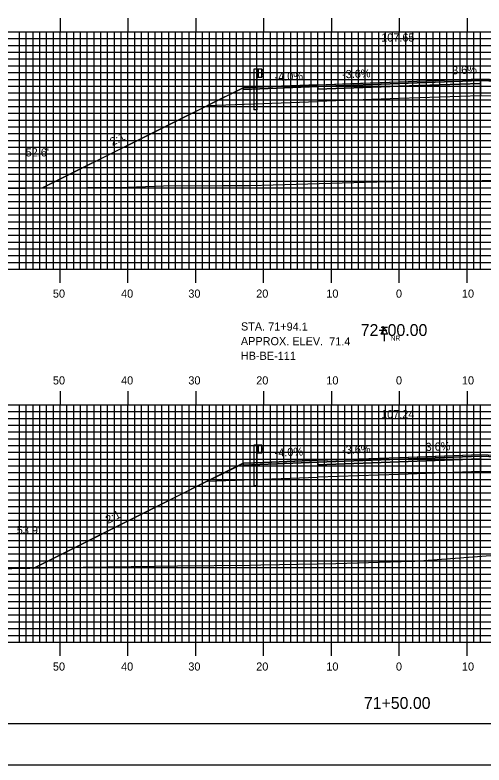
# Model space of a CAD drawing. Extents: x 1760610 to 1760954, y 442591 to 442811.
# Drawn here: x 1760719.5 to 1760788.7, y 442590.5 to 442701.2 of the extents above; entities that cross this region are included whole.
import ezdxf

# ---------------------------------------------------------------- set-up
doc = ezdxf.new("R2010")
doc.units = 0
for name, color, linetype in [('ANNOTATION', 7, 'Continuous'), ('BORDER', 7, 'Continuous'), ('BORING - NO REFUSAL', 7, 'Continuous'), ('D_Guardrail_Beam_Lt', 7, 'Continuous'), ('D_Roadway_Centerline', 7, 'Continuous'), ('D_Roadway_Centerline_Text', 7, 'Continuous'), ('D_Roadway_Edge_Shoulder', 7, 'Continuous'), ('D_Roadway_Edge_TW', 7, 'Continuous'), ('D_Roadway_Pavement', 7, 'Continuous'), ('D_Roadway_SlopeLines', 7, 'Continuous'), ('D_Roadway_SubGrade', 7, 'Continuous'), ('D_Text_Standard', 7, 'Continuous'), ('H_V ANNOTATION', 7, 'Continuous'), ('MAJOR', 7, 'Continuous'), ('MINOR', 7, 'Continuous'), ('PLOT BOUNDARY', 7, 'Continuous'), ('S_Roadway_Centerline', 7, 'Continuous')]:
    doc.layers.add(name, color=color, linetype=linetype)

msp = doc.modelspace()

# ---------------------------------------------------------------- linework, layer by layer
at = {"layer": 'BORDER'}
msp.add_lwpolyline([(1760626.61, 442596.67), (1760946.61, 442596.67), (1760946.61, 442806.67), (1760626.61, 442806.67)], close=True, dxfattribs=at)
at = {"layer": 'BORING - NO REFUSAL'}
for p, q in [((1760774.49, 442655.07), (1760773.53, 442655.07)), ((1760774.01, 442654.11), (1760774.01, 442653.05))]:
    msp.add_line(p, q, dxfattribs=at)
msp.add_lwpolyline([(1760774.01, 442655.07), (1760774.49, 442654.11), (1760773.53, 442654.11)], close=True, dxfattribs=at)
at = {"layer": 'D_Guardrail_Beam_Lt'}
for p, q in [((1760754.78, 442693.15), (1760754.78, 442687.15)), ((1760755.26, 442693.15), (1760754.78, 442693.15)), ((1760755.94, 442693.15), (1760755.26, 442693.15)), ((1760755.26, 442693.15), (1760755.26, 442691.98)), ((1760755.32, 442693.15), (1760755.32, 442691.98)), ((1760755.42, 442693.15), (1760755.42, 442691.98)), ((1760755.94, 442691.98), (1760755.94, 442693.15)), ((1760755.94, 442693.06), (1760756.02, 442693.05)), ((1760756.18, 442692.8), (1760755.98, 442692.66)), ((1760756.03, 442693.04), (1760756.18, 442692.94)), ((1760755.26, 442691.98), (1760755.94, 442691.98)), ((1760755.28, 442687.15), (1760755.28, 442691.98)), ((1760756.02, 442692.08), (1760755.94, 442692.06)), ((1760755.95, 442692.6), (1760755.95, 442692.53)), ((1760755.98, 442692.46), (1760756.18, 442692.33)), ((1760756.18, 442692.18), (1760756.03, 442692.08)), ((1760755.28, 442687.15), (1760754.78, 442687.15)), ((1760754.78, 442637.74), (1760754.78, 442631.74)), ((1760755.26, 442637.74), (1760754.78, 442637.74)), ((1760755.94, 442637.74), (1760755.26, 442637.74)), ((1760755.26, 442637.74), (1760755.26, 442636.57)), ((1760755.32, 442637.74), (1760755.32, 442636.57)), ((1760755.42, 442637.74), (1760755.42, 442636.57)), ((1760755.94, 442636.57), (1760755.94, 442637.74)), ((1760755.94, 442637.66), (1760756.02, 442637.64)), ((1760756.18, 442637.39), (1760755.98, 442637.26)), ((1760756.03, 442637.64), (1760756.18, 442637.54)), ((1760755.26, 442636.57), (1760755.94, 442636.57)), ((1760755.28, 442631.74), (1760755.28, 442636.57)), ((1760756.02, 442636.67), (1760755.94, 442636.66)), ((1760755.95, 442637.19), (1760755.95, 442637.12)), ((1760755.98, 442637.06), (1760756.18, 442636.92)), ((1760756.18, 442636.78), (1760756.03, 442636.68)), ((1760755.28, 442631.74), (1760754.78, 442631.74))]:
    msp.add_line(p, q, dxfattribs=at)
for centre, major_axis, start_param, end_param in [((1760756.03, 442692.6), (-0.0789, 0), 5.323254, 6.283185), ((1760756.01, 442693.01), (0.0417, 0), 0.959931, 1.376053), ((1760756.13, 442692.87), (0.0877, 0), 5.323254, 7.243116), ((1760756.03, 442692.53), (-0.0789, 0), 6.283185, 7.243116), ((1760756.01, 442692.12), (0.0417, 0), 4.907132, 5.323254), ((1760756.13, 442692.26), (0.0877, 0), 5.323254, 7.243116), ((1760756.01, 442637.6), (0.0417, 0), 0.959931, 1.376053), ((1760756.13, 442637.46), (0.0877, 0), 5.323254, 7.243116), ((1760756.03, 442637.19), (-0.0789, 0), 5.323254, 6.283185), ((1760756.03, 442637.12), (-0.0789, 0), 6.283185, 7.243116), ((1760756.01, 442636.71), (0.0417, 0), 4.907132, 5.323254), ((1760756.13, 442636.85), (0.0877, 0), 5.323254, 7.243116)]:
    msp.add_ellipse(centre, major_axis=major_axis, ratio=0.995501, start_param=start_param, end_param=end_param, dxfattribs=at)
at = {"layer": 'D_Roadway_Centerline'}
for points in [[(1760723.62, 442675.65), (1760747.92, 442687.8), (1760747.92, 442687.8), (1760749.52, 442688.6), (1760753.21, 442690.44), (1760753.22, 442690.44), (1760756.21, 442690.56), (1760756.22, 442690.56), (1760764.21, 442690.88), (1760764.23, 442690.88), (1760769.08, 442691.06), (1760776.21, 442691.32), (1760776.21, 442691.32), (1760784.04, 442691.6), (1760788.21, 442691.75), (1760788.22, 442691.75), (1760790.81, 442691.64), (1760796.21, 442691.43), (1760796.21, 442691.43), (1760797.9, 442691.36), (1760799.21, 442691.31), (1760803.96, 442688.93), (1760828.33, 442676.75), (1760828.33, 442676.75)], [(1760722.32, 442619.59), (1760722.34, 442619.6), (1760727.43, 442622.15), (1760747.91, 442632.39), (1760747.92, 442632.39), (1760751.51, 442634.19), (1760753.21, 442635.03), (1760753.21, 442635.04), (1760756.2, 442635.16), (1760756.21, 442635.16), (1760756.25, 442635.16), (1760764.21, 442635.48), (1760764.22, 442635.48), (1760776.21, 442635.91), (1760776.22, 442635.91), (1760780.32, 442636.06), (1760788.21, 442636.34), (1760789.01, 442636.31)]]:
    msp.add_lwpolyline(points, dxfattribs=at)
at = {"layer": 'D_Roadway_Edge_Shoulder'}
for points in [[(1760788.21, 442691.75), (1760796.21, 442691.43), (1760796.21, 442691.43), (1760799.21, 442691.31), (1760799.21, 442691.06), (1760788.21, 442691.5)], [(1760764.21, 442690.88), (1760756.21, 442690.56), (1760756.21, 442690.56), (1760753.21, 442690.44), (1760753.21, 442690.19), (1760764.21, 442690.63)], [(1760788.21, 442636.34), (1760796.21, 442636.02), (1760796.21, 442636.02), (1760799.21, 442635.9), (1760799.21, 442635.65), (1760788.21, 442636.09)], [(1760764.21, 442635.48), (1760756.21, 442635.16), (1760756.21, 442635.16), (1760753.21, 442635.04), (1760753.21, 442634.79), (1760764.21, 442635.23)]]:
    msp.add_lwpolyline(points, close=True, dxfattribs=at)
at = {"layer": 'D_Roadway_Edge_TW'}
for points in [[(1760764.21, 442690.63), (1760764.21, 442690.88), (1760776.21, 442691.32), (1760788.21, 442691.75), (1760788.21, 442691.5), (1760776.21, 442691.07)], [(1760788.21, 442691.75), (1760788.21, 442691.75), (1760788.21, 442691.5), (1760788.21, 442691.5)], [(1760764.21, 442635.23), (1760764.21, 442635.48), (1760776.21, 442635.91), (1760788.21, 442636.34), (1760788.21, 442636.09), (1760776.21, 442635.66)], [(1760788.21, 442636.34), (1760788.21, 442636.34), (1760788.21, 442636.09), (1760788.21, 442636.09)]]:
    msp.add_lwpolyline(points, close=True, dxfattribs=at)
at = {"layer": 'D_Roadway_Pavement'}
for points in [[(1760764.21, 442690.22), (1760764.21, 442690.63), (1760776.21, 442691.07), (1760788.21, 442691.5), (1760788.21, 442691.08), (1760776.21, 442690.65)], [(1760788.21, 442691.5), (1760788.21, 442691.5), (1760788.21, 442691.08), (1760788.21, 442691.08)], [(1760764.21, 442634.81), (1760764.21, 442635.23), (1760776.21, 442635.66), (1760788.21, 442636.09), (1760788.21, 442635.68), (1760776.21, 442635.24)], [(1760788.21, 442636.09), (1760788.21, 442636.09), (1760788.21, 442635.68), (1760788.21, 442635.68)]]:
    msp.add_lwpolyline(points, close=True, dxfattribs=at)
for points in [[(1760764.21, 442690.63), (1760764.21, 442690.22)], [(1760788.21, 442691.5), (1760788.21, 442691.08)], [(1760788.21, 442691.5), (1760788.21, 442691.08)], [(1760764.21, 442635.23), (1760764.21, 442634.81)], [(1760788.21, 442636.09), (1760788.21, 442635.68)], [(1760788.21, 442636.09), (1760788.21, 442635.68)]]:
    msp.add_lwpolyline(points, dxfattribs=at)
at = {"layer": 'D_Roadway_SlopeLines'}
for points in [[(1760753.21, 442690.44), (1760723.62, 442675.65)], [(1760753.21, 442635.04), (1760722.32, 442619.59)]]:
    msp.add_lwpolyline(points, dxfattribs=at)
at = {"layer": 'D_Roadway_SubGrade'}
for points in [[(1760764.21, 442690.22), (1760764.21, 442690.63), (1760753.21, 442690.19), (1760753.21, 442690.44), (1760747.92, 442687.8), (1760764.21, 442688.38)], [(1760764.21, 442688.38), (1760764.21, 442690.22), (1760776.21, 442690.65), (1760788.21, 442691.08), (1760788.21, 442689.25), (1760776.21, 442688.82)], [(1760788.21, 442691.08), (1760788.21, 442691.5), (1760799.21, 442691.06), (1760799.21, 442691.31), (1760803.96, 442688.93), (1760788.21, 442689.25)], [(1760788.21, 442691.08), (1760788.21, 442691.08), (1760788.21, 442689.25), (1760788.21, 442689.25)], [(1760764.21, 442634.81), (1760764.21, 442635.23), (1760753.21, 442634.79), (1760753.21, 442635.04), (1760747.92, 442632.39), (1760764.21, 442632.98)], [(1760764.21, 442632.98), (1760764.21, 442634.81), (1760776.21, 442635.24), (1760788.21, 442635.68), (1760788.21, 442633.84), (1760776.21, 442633.41)], [(1760788.21, 442635.68), (1760788.21, 442636.09), (1760799.21, 442635.65), (1760799.21, 442635.9), (1760803.96, 442633.53), (1760788.21, 442633.84)], [(1760788.21, 442635.68), (1760788.21, 442635.68), (1760788.21, 442633.84), (1760788.21, 442633.84)]]:
    msp.add_lwpolyline(points, close=True, dxfattribs=at)
at = {"layer": 'MAJOR'}
for p, q in [((1760726.21, 442700.67), (1760726.21, 442698.67)), ((1760736.21, 442700.67), (1760736.21, 442698.67)), ((1760746.21, 442700.67), (1760746.21, 442698.67)), ((1760756.21, 442700.67), (1760756.21, 442698.67)), ((1760766.21, 442700.67), (1760766.21, 442698.67)), ((1760776.21, 442700.67), (1760776.21, 442698.67)), ((1760786.21, 442700.67), (1760786.21, 442698.67)), ((1760636.21, 442698.67), (1760916.21, 442698.67)), ((1760636.21, 442698.67), (1760916.21, 442698.67)), ((1760726.21, 442663.67), (1760726.21, 442698.67)), ((1760736.21, 442663.67), (1760736.21, 442698.67)), ((1760746.21, 442663.67), (1760746.21, 442698.67)), ((1760756.21, 442663.67), (1760756.21, 442698.67)), ((1760766.21, 442663.67), (1760766.21, 442698.67)), ((1760776.21, 442663.67), (1760776.21, 442698.67)), ((1760786.21, 442663.67), (1760786.21, 442698.67)), ((1760636.21, 442693.67), (1760916.21, 442693.67)), ((1760636.21, 442688.67), (1760916.21, 442688.67)), ((1760636.21, 442683.67), (1760916.21, 442683.67)), ((1760636.21, 442678.67), (1760916.21, 442678.67)), ((1760636.21, 442673.67), (1760916.21, 442673.67)), ((1760636.21, 442668.67), (1760916.21, 442668.67)), ((1760636.21, 442663.67), (1760916.21, 442663.67)), ((1760636.21, 442663.67), (1760916.21, 442663.67)), ((1760726.21, 442661.66), (1760726.21, 442663.67)), ((1760736.21, 442661.66), (1760736.21, 442663.67)), ((1760746.21, 442661.66), (1760746.21, 442663.67)), ((1760756.21, 442661.66), (1760756.21, 442663.67)), ((1760766.21, 442661.66), (1760766.21, 442663.67)), ((1760776.21, 442661.66), (1760776.21, 442663.67)), ((1760786.21, 442661.66), (1760786.21, 442663.67)), ((1760726.21, 442645.67), (1760726.21, 442643.67)), ((1760736.21, 442645.67), (1760736.21, 442643.67)), ((1760746.21, 442645.67), (1760746.21, 442643.67)), ((1760756.21, 442645.67), (1760756.21, 442643.67)), ((1760766.21, 442645.67), (1760766.21, 442643.67)), ((1760776.21, 442645.67), (1760776.21, 442643.67)), ((1760786.21, 442645.67), (1760786.21, 442643.67)), ((1760636.21, 442643.67), (1760916.21, 442643.67)), ((1760636.21, 442643.67), (1760916.21, 442643.67)), ((1760726.21, 442608.67), (1760726.21, 442643.67)), ((1760736.21, 442608.67), (1760736.21, 442643.67)), ((1760746.21, 442608.67), (1760746.21, 442643.67)), ((1760756.21, 442608.67), (1760756.21, 442643.67)), ((1760766.21, 442608.67), (1760766.21, 442643.67)), ((1760776.21, 442608.67), (1760776.21, 442643.67)), ((1760786.21, 442608.67), (1760786.21, 442643.67)), ((1760636.21, 442638.67), (1760916.21, 442638.67)), ((1760636.21, 442633.67), (1760916.21, 442633.67)), ((1760636.21, 442628.67), (1760916.21, 442628.67)), ((1760636.21, 442623.67), (1760916.21, 442623.67)), ((1760636.21, 442618.67), (1760916.21, 442618.67)), ((1760636.21, 442613.67), (1760916.21, 442613.67)), ((1760636.21, 442608.67), (1760916.21, 442608.67)), ((1760636.21, 442608.67), (1760916.21, 442608.67)), ((1760726.21, 442606.66), (1760726.21, 442608.67)), ((1760736.21, 442606.66), (1760736.21, 442608.67)), ((1760746.21, 442606.66), (1760746.21, 442608.67)), ((1760756.21, 442606.66), (1760756.21, 442608.67)), ((1760766.21, 442606.66), (1760766.21, 442608.67)), ((1760776.21, 442606.66), (1760776.21, 442608.67)), ((1760786.21, 442606.66), (1760786.21, 442608.67))]:
    msp.add_line(p, q, dxfattribs=at)
at = {"layer": 'MINOR'}
for p, q in [((1760720.21, 442663.67), (1760720.21, 442698.67)), ((1760721.21, 442663.67), (1760721.21, 442698.67)), ((1760722.21, 442663.67), (1760722.21, 442698.67)), ((1760723.21, 442663.67), (1760723.21, 442698.67)), ((1760724.21, 442663.67), (1760724.21, 442698.67)), ((1760725.21, 442663.67), (1760725.21, 442698.67)), ((1760727.21, 442663.67), (1760727.21, 442698.67)), ((1760728.21, 442663.67), (1760728.21, 442698.67)), ((1760729.21, 442663.67), (1760729.21, 442698.67)), ((1760730.21, 442663.67), (1760730.21, 442698.67)), ((1760731.21, 442663.67), (1760731.21, 442698.67)), ((1760732.21, 442663.67), (1760732.21, 442698.67)), ((1760733.21, 442663.67), (1760733.21, 442698.67)), ((1760734.21, 442663.67), (1760734.21, 442698.67)), ((1760735.21, 442663.67), (1760735.21, 442698.67)), ((1760737.21, 442663.67), (1760737.21, 442698.67)), ((1760738.21, 442663.67), (1760738.21, 442698.67)), ((1760739.21, 442663.67), (1760739.21, 442698.67)), ((1760740.21, 442663.67), (1760740.21, 442698.67)), ((1760741.21, 442663.67), (1760741.21, 442698.67)), ((1760742.21, 442663.67), (1760742.21, 442698.67)), ((1760743.21, 442663.67), (1760743.21, 442698.67)), ((1760744.21, 442663.67), (1760744.21, 442698.67)), ((1760745.21, 442663.67), (1760745.21, 442698.67)), ((1760747.21, 442663.67), (1760747.21, 442698.67)), ((1760748.21, 442663.67), (1760748.21, 442698.67)), ((1760749.21, 442663.67), (1760749.21, 442698.67)), ((1760750.21, 442663.67), (1760750.21, 442698.67)), ((1760751.21, 442663.67), (1760751.21, 442698.67)), ((1760752.21, 442663.67), (1760752.21, 442698.67)), ((1760753.21, 442663.67), (1760753.21, 442698.67)), ((1760754.21, 442663.67), (1760754.21, 442698.67)), ((1760755.21, 442663.67), (1760755.21, 442698.67)), ((1760757.21, 442663.67), (1760757.21, 442698.67)), ((1760758.21, 442663.67), (1760758.21, 442698.67)), ((1760759.21, 442663.67), (1760759.21, 442698.67)), ((1760760.21, 442663.67), (1760760.21, 442698.67)), ((1760761.21, 442663.67), (1760761.21, 442698.67)), ((1760762.21, 442663.67), (1760762.21, 442698.67)), ((1760763.21, 442663.67), (1760763.21, 442698.67)), ((1760764.21, 442663.67), (1760764.21, 442698.67)), ((1760765.21, 442663.67), (1760765.21, 442698.67)), ((1760767.21, 442663.67), (1760767.21, 442698.67)), ((1760768.21, 442663.67), (1760768.21, 442698.67)), ((1760769.21, 442663.67), (1760769.21, 442698.67)), ((1760770.21, 442663.67), (1760770.21, 442698.67)), ((1760771.21, 442663.67), (1760771.21, 442698.67)), ((1760772.21, 442663.67), (1760772.21, 442698.67)), ((1760773.21, 442663.67), (1760773.21, 442698.67)), ((1760774.21, 442663.67), (1760774.21, 442698.67)), ((1760775.21, 442663.67), (1760775.21, 442698.67)), ((1760777.21, 442663.67), (1760777.21, 442698.67)), ((1760778.21, 442663.67), (1760778.21, 442698.67)), ((1760779.21, 442663.67), (1760779.21, 442698.67)), ((1760780.21, 442663.67), (1760780.21, 442698.67)), ((1760781.21, 442663.67), (1760781.21, 442698.67)), ((1760782.21, 442663.67), (1760782.21, 442698.67)), ((1760783.21, 442663.67), (1760783.21, 442698.67)), ((1760784.21, 442663.67), (1760784.21, 442698.67)), ((1760785.21, 442663.67), (1760785.21, 442698.67)), ((1760787.21, 442663.67), (1760787.21, 442698.67)), ((1760788.21, 442663.67), (1760788.21, 442698.67)), ((1760636.21, 442697.67), (1760916.21, 442697.67)), ((1760636.21, 442696.67), (1760916.21, 442696.67)), ((1760636.21, 442695.67), (1760916.21, 442695.67)), ((1760636.21, 442694.67), (1760916.21, 442694.67)), ((1760636.21, 442692.67), (1760916.21, 442692.67)), ((1760636.21, 442691.67), (1760916.21, 442691.67)), ((1760636.21, 442690.67), (1760916.21, 442690.67)), ((1760636.21, 442689.67), (1760916.21, 442689.67)), ((1760636.21, 442687.67), (1760916.21, 442687.67)), ((1760636.21, 442686.67), (1760916.21, 442686.67)), ((1760636.21, 442685.67), (1760916.21, 442685.67)), ((1760636.21, 442684.67), (1760916.21, 442684.67)), ((1760636.21, 442682.67), (1760916.21, 442682.67)), ((1760636.21, 442681.67), (1760916.21, 442681.67)), ((1760636.21, 442680.67), (1760916.21, 442680.67)), ((1760636.21, 442679.67), (1760916.21, 442679.67)), ((1760636.21, 442677.67), (1760916.21, 442677.67)), ((1760636.21, 442676.67), (1760916.21, 442676.67)), ((1760636.21, 442675.67), (1760916.21, 442675.67)), ((1760636.21, 442674.67), (1760916.21, 442674.67)), ((1760636.21, 442672.67), (1760916.21, 442672.67)), ((1760636.21, 442671.67), (1760916.21, 442671.67)), ((1760636.21, 442670.67), (1760916.21, 442670.67)), ((1760636.21, 442669.67), (1760916.21, 442669.67)), ((1760636.21, 442667.67), (1760916.21, 442667.67)), ((1760636.21, 442666.67), (1760916.21, 442666.67)), ((1760636.21, 442665.67), (1760916.21, 442665.67)), ((1760636.21, 442664.67), (1760916.21, 442664.67)), ((1760720.21, 442608.67), (1760720.21, 442643.67)), ((1760721.21, 442608.67), (1760721.21, 442643.67)), ((1760722.21, 442608.67), (1760722.21, 442643.67)), ((1760723.21, 442608.67), (1760723.21, 442643.67)), ((1760724.21, 442608.67), (1760724.21, 442643.67)), ((1760725.21, 442608.67), (1760725.21, 442643.67)), ((1760727.21, 442608.67), (1760727.21, 442643.67)), ((1760728.21, 442608.67), (1760728.21, 442643.67)), ((1760729.21, 442608.67), (1760729.21, 442643.67)), ((1760730.21, 442608.67), (1760730.21, 442643.67)), ((1760731.21, 442608.67), (1760731.21, 442643.67)), ((1760732.21, 442608.67), (1760732.21, 442643.67)), ((1760733.21, 442608.67), (1760733.21, 442643.67)), ((1760734.21, 442608.67), (1760734.21, 442643.67)), ((1760735.21, 442608.67), (1760735.21, 442643.67)), ((1760737.21, 442608.67), (1760737.21, 442643.67)), ((1760738.21, 442608.67), (1760738.21, 442643.67)), ((1760739.21, 442608.67), (1760739.21, 442643.67)), ((1760740.21, 442608.67), (1760740.21, 442643.67)), ((1760741.21, 442608.67), (1760741.21, 442643.67)), ((1760742.21, 442608.67), (1760742.21, 442643.67)), ((1760743.21, 442608.67), (1760743.21, 442643.67)), ((1760744.21, 442608.67), (1760744.21, 442643.67)), ((1760745.21, 442608.67), (1760745.21, 442643.67)), ((1760747.21, 442608.67), (1760747.21, 442643.67)), ((1760748.21, 442608.67), (1760748.21, 442643.67)), ((1760749.21, 442608.67), (1760749.21, 442643.67)), ((1760750.21, 442608.67), (1760750.21, 442643.67)), ((1760751.21, 442608.67), (1760751.21, 442643.67)), ((1760752.21, 442608.67), (1760752.21, 442643.67)), ((1760753.21, 442608.67), (1760753.21, 442643.67)), ((1760754.21, 442608.67), (1760754.21, 442643.67)), ((1760755.21, 442608.67), (1760755.21, 442643.67)), ((1760757.21, 442608.67), (1760757.21, 442643.67)), ((1760758.21, 442608.67), (1760758.21, 442643.67)), ((1760759.21, 442608.67), (1760759.21, 442643.67)), ((1760760.21, 442608.67), (1760760.21, 442643.67)), ((1760761.21, 442608.67), (1760761.21, 442643.67)), ((1760762.21, 442608.67), (1760762.21, 442643.67)), ((1760763.21, 442608.67), (1760763.21, 442643.67)), ((1760764.21, 442608.67), (1760764.21, 442643.67)), ((1760765.21, 442608.67), (1760765.21, 442643.67)), ((1760767.21, 442608.67), (1760767.21, 442643.67)), ((1760768.21, 442608.67), (1760768.21, 442643.67)), ((1760769.21, 442608.67), (1760769.21, 442643.67)), ((1760770.21, 442608.67), (1760770.21, 442643.67)), ((1760771.21, 442608.67), (1760771.21, 442643.67)), ((1760772.21, 442608.67), (1760772.21, 442643.67)), ((1760773.21, 442608.67), (1760773.21, 442643.67)), ((1760774.21, 442608.67), (1760774.21, 442643.67)), ((1760775.21, 442608.67), (1760775.21, 442643.67)), ((1760777.21, 442608.67), (1760777.21, 442643.67)), ((1760778.21, 442608.67), (1760778.21, 442643.67)), ((1760779.21, 442608.67), (1760779.21, 442643.67)), ((1760780.21, 442608.67), (1760780.21, 442643.67)), ((1760781.21, 442608.67), (1760781.21, 442643.67)), ((1760782.21, 442608.67), (1760782.21, 442643.67)), ((1760783.21, 442608.67), (1760783.21, 442643.67)), ((1760784.21, 442608.67), (1760784.21, 442643.67)), ((1760785.21, 442608.67), (1760785.21, 442643.67)), ((1760787.21, 442608.67), (1760787.21, 442643.67)), ((1760788.21, 442608.67), (1760788.21, 442643.67)), ((1760636.21, 442642.67), (1760916.21, 442642.67)), ((1760636.21, 442641.67), (1760916.21, 442641.67)), ((1760636.21, 442640.67), (1760916.21, 442640.67)), ((1760636.21, 442639.67), (1760916.21, 442639.67)), ((1760636.21, 442637.67), (1760916.21, 442637.67)), ((1760636.21, 442636.67), (1760916.21, 442636.67)), ((1760636.21, 442635.67), (1760916.21, 442635.67)), ((1760636.21, 442634.67), (1760916.21, 442634.67)), ((1760636.21, 442632.67), (1760916.21, 442632.67)), ((1760636.21, 442631.67), (1760916.21, 442631.67)), ((1760636.21, 442630.67), (1760916.21, 442630.67)), ((1760636.21, 442629.67), (1760916.21, 442629.67)), ((1760636.21, 442627.67), (1760916.21, 442627.67)), ((1760636.21, 442626.67), (1760916.21, 442626.67)), ((1760636.21, 442625.67), (1760916.21, 442625.67)), ((1760636.21, 442624.67), (1760916.21, 442624.67)), ((1760636.21, 442622.67), (1760916.21, 442622.67)), ((1760636.21, 442621.67), (1760916.21, 442621.67)), ((1760636.21, 442620.67), (1760916.21, 442620.67)), ((1760636.21, 442619.67), (1760916.21, 442619.67)), ((1760636.21, 442617.67), (1760916.21, 442617.67)), ((1760636.21, 442616.67), (1760916.21, 442616.67)), ((1760636.21, 442615.67), (1760916.21, 442615.67)), ((1760636.21, 442614.67), (1760916.21, 442614.67)), ((1760636.21, 442612.67), (1760916.21, 442612.67)), ((1760636.21, 442611.67), (1760916.21, 442611.67)), ((1760636.21, 442610.67), (1760916.21, 442610.67)), ((1760636.21, 442609.67), (1760916.21, 442609.67))]:
    msp.add_line(p, q, dxfattribs=at)
at = {"layer": 'PLOT BOUNDARY'}
msp.add_lwpolyline([(1760610.43, 442590.55), (1760950.43, 442590.55), (1760950.43, 442810.55), (1760610.43, 442810.55)], close=True, dxfattribs=at)
at = {"layer": 'S_Roadway_Centerline'}
for points in [[(1760711.92, 442675.53), (1760730.31, 442675.71), (1760734.82, 442675.73), (1760741.47, 442675.95), (1760750.12, 442676), (1760754.25, 442676.03), (1760757.6, 442676.1), (1760772.92, 442676.54), (1760780.57, 442676.71), (1760788.45, 442676.73), (1760796.99, 442676.8), (1760802.85, 442676.8), (1760818.56, 442676.53), (1760821.97, 442676.54), (1760825.1, 442676.61), (1760834.38, 442677.01)], [(1760711.14, 442619.36), (1760729.61, 442619.74), (1760733.29, 442619.76), (1760743.51, 442619.94), (1760754.29, 442620.03), (1760755.8, 442620.05), (1760766.86, 442620.28), (1760778.13, 442620.62), (1760778.5, 442620.63), (1760800.23, 442622.24), (1760802.43, 442622.22), (1760813.3, 442620.56), (1760823.06, 442620.13), (1760826.5, 442620.08), (1760845.03, 442620.4)]]:
    msp.add_lwpolyline(points, dxfattribs=at)

# ---------------------------------------------------------------- texts
at = {"layer": 'ANNOTATION'}
for s, rotation, p in [('-4.0%', 2.2908, (1760757.85, 442691.43)), ('-3.6%', 2.0618, (1760767.8, 442691.81)), ('3.6%', 2.0618, (1760784.03, 442692.4)), ('2:1', 26.564, (1760733.92, 442681.83)), ('-4.0%', 2.2905, (1760757.86, 442636.02)), ('-3.6%', 2.0618, (1760767.8, 442636.41)), ('3.6%', 2.0618, (1760780.12, 442636.85)), ('2:1', 26.5642, (1760733.27, 442626.1))]:
    msp.add_text(s, height=1.2, rotation=rotation, dxfattribs=at).set_placement(p)
at = {"layer": 'BORING - NO REFUSAL'}
for s, p in [('STA. 71+94.1', (1760752.87, 442654.63)), ('APPROX. ELEV.  71.4', (1760752.86, 442652.47)), ('HB-BE-111', (1760752.85, 442650.31))]:
    msp.add_text(s, height=1.2, rotation=359.8142, dxfattribs=at).set_placement(p)
msp.add_text('NR', height=0.7, dxfattribs=at).set_placement((1760774.95, 442653.15))
at = {"layer": 'D_Roadway_Centerline'}
for s, p in [('C', (1760776.21, 442691.32)), ('L', (1760776.21, 442691.31)), ('C', (1760776.21, 442635.91)), ('L', (1760776.21, 442635.9))]:
    msp.add_text(s, height=0.0146, dxfattribs=at).set_placement(p)
at = {"layer": 'D_Roadway_Centerline_Text'}
for s, p in [('107.65', (1760773.55, 442697.24)), ('107.24', (1760773.53, 442641.68))]:
    msp.add_text(s, height=1.2, dxfattribs=at).set_placement(p)
at = {"layer": 'D_Text_Standard'}
for s, p in [("52.6'", (1760721.12, 442680.3)), ("53.9'", (1760719.81, 442624.6))]:
    msp.add_text(s, height=1.2, dxfattribs=at).set_placement(p)
at = {"layer": 'H_V ANNOTATION'}
for s, height, p in [('50', 1.2, (1760725.14, 442659.47)), ('40', 1.2, (1760735.19, 442659.47)), ('30', 1.2, (1760745.11, 442659.47)), ('20', 1.2, (1760755.12, 442659.47)), ('10', 1.2, (1760765.46, 442659.47)), ('0', 1.2, (1760775.73, 442659.47)), ('10', 1.2, (1760785.46, 442659.47)), ('72+00.00', 1.75, (1760770.53, 442653.82)), ('50', 1.2, (1760725.14, 442646.67)), ('40', 1.2, (1760735.19, 442646.67)), ('30', 1.2, (1760745.11, 442646.67)), ('20', 1.2, (1760755.12, 442646.67)), ('10', 1.2, (1760765.46, 442646.67)), ('0', 1.2, (1760775.73, 442646.67)), ('10', 1.2, (1760785.46, 442646.67)), ('50', 1.2, (1760725.14, 442604.47)), ('40', 1.2, (1760735.19, 442604.47)), ('30', 1.2, (1760745.11, 442604.47)), ('20', 1.2, (1760755.12, 442604.47)), ('10', 1.2, (1760765.46, 442604.47)), ('0', 1.2, (1760775.73, 442604.47)), ('10', 1.2, (1760785.46, 442604.47)), ('71+50.00', 1.75, (1760771, 442598.82))]:
    msp.add_text(s, height=height, dxfattribs=at).set_placement(p)

doc.saveas('drawing.dxf')
